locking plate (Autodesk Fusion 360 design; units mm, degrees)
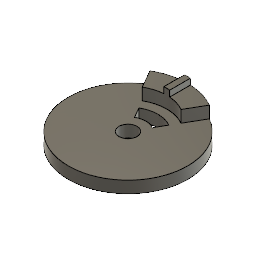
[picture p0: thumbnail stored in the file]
sketch "Sketch1" plane through (0, 0, 0) normal (0, 1, 0) x axis (1, 0, 0)
  circle C1 centre (0, 0) radius 50
  point P1 (0, 0)
  point P2 (0, 0)
  coincident P1 P2
  dimension "d1" diameter C1 = 100
extrude "Extrude1" new body sketch "Sketch1" along normal blind 10
sketch "Sketch2" plane through (0, 10, 0) normal (0, 1, 0) x axis (-1, 0, 0)
  line L1 (-16.25, -28.1458) -> (-25, -43.3013)
  line L2 (25, -43.3013) -> (16.25, -28.1458)
  line L3 (0, -32.5) -> (0, 0)
  circle C1 centre (0, 0) radius 50
  circle C2 centre (0, 0) radius 32.5
  point P4 (-25, -43.3013)
  point P5 (-16.25, -28.1458)
  point P6 (16.25, -28.1458)
  point P7 (25, -43.3013)
  point P3 (0, 0)
  point P8 (0, 0)
  point P9 (0, -32.5)
  point P1 (0, 0)
  concentric C1 C2
  coincident C1 P4
  coincident C2 P5
  coincident C2 P6
  coincident C1 P7
  coincident P3 P8
  coincident C2 P9
  vertical L3
  coincident P1 L1
  coincident P3 L2
  dimension "d4" diameter C2 = 65
  dimension "d5" angle L1 L3 = 30
  dimension "d6" angle L2 L3 = 30 (= "d5")
extrude "Extrude2" add sketch "Sketch2" profile of C1 C2 L1 L2 along normal blind 10
sketch "Sketch3" plane through (0, 10, 0) normal (0, 1, 0) x axis (-1, 0, 0)
  line L1 (25, -43.3013) -> (16.25, -28.1458)
  line L2 (-16.25, -28.1458) -> (-25, -43.3013)
  line L3 (-25, -43.3013) -> (-16.25, -28.1458)
  line L4 (16.25, -28.1458) -> (25, -43.3013)
  line L5 (-12.5, -21.6506) -> (-7.5, -12.9904)
  line L6 (12.5, -21.6506) -> (7.5, -12.9904)
  arc A1 centre (0, 0) radius 50 clockwise from (-25, -43.3013) to (25, -43.3013)
  arc A2 centre (0, 0) radius 32.5 clockwise from (16.25, -28.1458) to (-16.25, -28.1458)
  circle C1 centre (0, 0) radius 25
  circle C2 centre (0, 0) radius 15
  point P13 (-7.5, -12.9904)
  point P14 (-12.5, -21.6506)
  point P16 (12.5, -21.6506)
  point P15 (7.5, -12.9904)
  concentric A1 C1
  concentric C1 C2
  coincident C2 P13
  coincident C1 P14
  coincident C1 P16
  coincident C2 P15
  collinear L1 L6
  collinear L3 L5
  dimension "d9" diameter C2 = 30
  dimension "d10" diameter C1 = 50
extrude "Extrude3" cut sketch "Sketch3" profile of C1 C2 L5 L6 no distance stored
sketch "Sketch4" plane through (0, 10, 0) normal (0, 1, 0) x axis (-1, 0, 0)
  line L1 (12.5, -21.6506) -> (7.5, -12.9904)
  line L2
  line L3 (25, -43.3013) -> (16.25, -28.1458)
  line L4 (-16.25, -28.1458) -> (-25, -43.3013)
  arc A1 centre (0, 0) radius 15 clockwise from (7.5, -12.9904) to (-7.5, -12.9904)
  arc A2 centre (0, 0) radius 25 clockwise from (12.5, -21.6506) to (-12.5, -21.6506)
  arc A3 centre (0, 0) radius 50 clockwise from (-25, -43.3013) to (25, -43.3013)
  arc A4 centre (0, 0) radius 32.5 clockwise from (16.25, -28.1458) to (-16.25, -28.1458)
  circle C1 centre (0, 0) radius 7.5
  concentric A1 C1
  dimension "d12" diameter C1 = 15
extrude "Extrude4" cut sketch "Sketch4" profile of C1 no distance stored
sketch "Sketch5" plane through (0, 20, 0) normal (0, 1, 0) x axis (-1, 0, 0)
  line L1 (16.25, -28.1458) -> (25, -43.3013)
  line L2 (-25, -43.3013) -> (-16.25, -28.1458)
  line L3 (-2.5, -55) -> (2.5, -55)
  line L4 (-2.5, -30) -> (-2.5, -55)
  line L5 (2.5, -30) -> (-2.5, -30)
  line L6 (2.5, -55) -> (2.5, -30)
  line L7 (-2.5, -30) -> (2.5, -55)
  line L8 (2.5, -30) -> (-2.5, -55)
  arc A1 centre (0, 0) radius 50 clockwise from (25, -43.3013) to (-25, -43.3013)
  arc A2 centre (0, 0) radius 32.5 clockwise from (16.25, -28.1458) to (-16.25, -28.1458)
  point P11 (0, -42.5)
  point P1 (0, 0)
  point P7 (2.5, -55)
  point P8 (-2.5, -55)
  point P9 (-2.5, -30)
  perpendicular L3 L4
  parallel L3 L5
  parallel L4 L6
  horizontal L3
  coincident L7 P11
  coincident L8 P11
  vertical P1 P11
  dimension "d14" distance P7 P8 = 5
  dimension "d15" distance P8 P9 = 25
  dimension "d16" distance P1 P9 = 30
extrude "Extrude5" add sketch "Sketch5" profile of A1 A2 L4 L6 along normal blind 5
